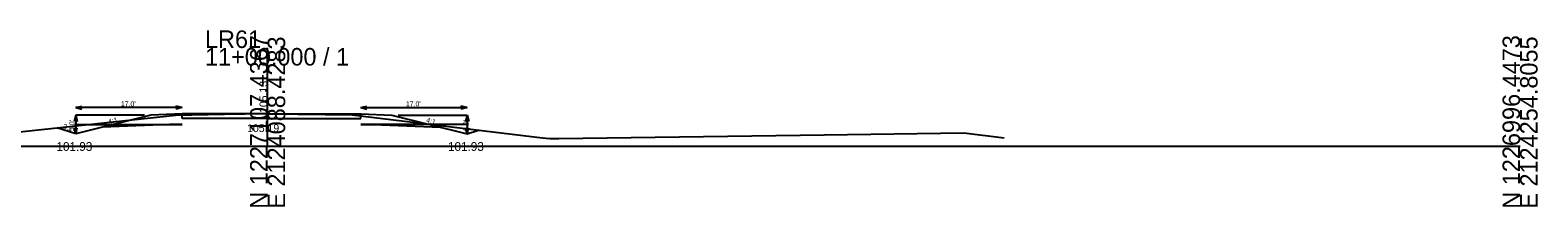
# Model space of a CAD drawing. Extents: x -26 to 1403, y -10 to 9574.
# Drawn here: x 1162.1 to 1402.8, y 990.3 to 1018.5 of the extents above; entities that cross this region are included whole.
import ezdxf

# ---------------------------------------------------------------- set-up
doc = ezdxf.new("R2010")
doc.units = 0
for name, color, linetype in [('XS_CELL', 7, 'Continuous'), ('XS_P_FINISHED_GRADE', 7, 'Continuous'), ('XS_P_FINISHED_GRADE_ELEV_TX', 7, 'Continuous'), ('XS_P_SUBGRADE_GRANULAR', 7, 'Continuous'), ('XS_P_SUBGRADE_PAVEMENT', 7, 'Continuous'), ('XS_P_TX_CLEARZONE', 7, 'Continuous'), ('XS_P_TX_DCH', 7, 'Continuous'), ('XS_P_TX_FS_BS', 7, 'Continuous'), ('XS_X_GROUND', 7, 'Continuous'), ('XS_X_GROUND_TX', 7, 'Continuous')]:
    doc.layers.add(name, color=color, linetype=linetype)

msp = doc.modelspace()

# ---------------------------------------------------------------- linework, layer by layer
at = {"layer": 'XS_CELL'}
for p, q in [((1200, 1000), (1200, 1015.64)), ((1000, 1000), (1200, 1000)), ((1200, 1000), (1400, 1000))]:
    msp.add_line(p, q, dxfattribs=at)
at = {"layer": 'XS_P_FINISHED_GRADE'}
for p, q in [((1181.35, 1004.93), (1169.35, 1001.93)), ((1186.35, 1005.13), (1181.35, 1004.93)), ((1200, 1005.13), (1186.35, 1005.13)), ((1200, 1005.13), (1214.86, 1005.13)), ((1214.86, 1005.13), (1219.86, 1004.93)), ((1219.86, 1004.93), (1231.87, 1001.93)), ((1169.35, 1001.93), (1166.36, 1002.93)), ((1231.87, 1001.93), (1233.66, 1002.53))]:
    msp.add_line(p, q, dxfattribs=at)
at = {"layer": 'XS_P_SUBGRADE_GRANULAR'}
for p, q in [((1169.15, 1003.43), (1186.35, 1003.43)), ((1184.35, 1003.43), (1173.63, 1003)), ((1186.35, 1003.43), (1184.35, 1003.43)), ((1232.07, 1003.43), (1214.86, 1003.43)), ((1214.86, 1003.43), (1216.86, 1003.43)), ((1216.86, 1003.43), (1227.58, 1003))]:
    msp.add_line(p, q, dxfattribs=at)
at = {"layer": 'XS_P_SUBGRADE_PAVEMENT'}
for p, q in [((1186.35, 1004.38), (1186.35, 1005.13)), ((1200, 1004.38), (1186.35, 1004.38)), ((1200, 1004.38), (1214.86, 1004.38)), ((1214.86, 1004.38), (1214.86, 1005.13))]:
    msp.add_line(p, q, dxfattribs=at)
at = {"layer": 'XS_P_TX_CLEARZONE'}
for p, q in [((1169.35, 1006.13), (1170.35, 1006.38)), ((1186.35, 1006.13), (1185.35, 1006.38)), ((1214.86, 1006.13), (1215.86, 1006.38)), ((1231.87, 1006.13), (1230.87, 1006.38)), ((1169.35, 1004.93), (1169.1, 1003.93)), ((1169.35, 1006.13), (1170.35, 1005.88)), ((1186.35, 1006.13), (1169.35, 1006.13)), ((1169.35, 1004.93), (1169.6, 1003.93)), ((1169.35, 1004.93), (1169.35, 1001.93)), ((1180.35, 1004.93), (1169.35, 1004.93)), ((1186.35, 1006.13), (1185.35, 1005.88)), ((1214.86, 1006.13), (1215.86, 1005.88)), ((1214.86, 1006.13), (1231.87, 1006.13)), ((1220.86, 1004.93), (1231.87, 1004.93)), ((1231.87, 1006.13), (1230.87, 1005.88)), ((1231.87, 1004.93), (1231.62, 1003.93)), ((1231.87, 1004.93), (1231.87, 1001.93)), ((1231.87, 1004.93), (1232.12, 1003.93)), ((1169.35, 1001.93), (1169.1, 1002.93)), ((1169.35, 1001.93), (1169.6, 1002.93)), ((1231.87, 1001.93), (1231.62, 1002.93)), ((1231.87, 1001.93), (1232.12, 1002.93))]:
    msp.add_line(p, q, dxfattribs=at)
at = {"layer": 'XS_X_GROUND'}
for p, q in [((1156.87, 1001.92), (1185.3, 1004.93)), ((1185.3, 1004.93), (1193.09, 1005.08)), ((1193.09, 1005.08), (1199.77, 1005.19)), ((1199.77, 1005.19), (1204.85, 1005.11)), ((1204.85, 1005.11), (1213.5, 1004.96)), ((1213.5, 1004.96), (1243.9, 1001.3)), ((1246.49, 1001.21), (1288.88, 1001.79)), ((1288.88, 1001.79), (1311.2, 1002.09)), ((1311.2, 1002.09), (1317.61, 1001.33)), ((1243.9, 1001.3), (1245.06, 1001.21)), ((1245.06, 1001.21), (1246.49, 1001.21))]:
    msp.add_line(p, q, dxfattribs=at)

# ---------------------------------------------------------------- texts
at = {"layer": 'XS_CELL'}
for s, p in [('LR61', (1190, 1015.64)), ('11+00.000 / 1', (1190, 1012.84))]:
    msp.add_text(s, height=2.8, dxfattribs=at).set_placement(p)
for s, p in [('N 1227107.4367', (1200, 990)), ('E 2124088.4283', (1202.8, 990)), ('N 1226996.4473', (1400, 990)), ('E 2124254.8055', (1402.8, 990))]:
    msp.add_text(s, height=2.8, rotation=90, dxfattribs=at).set_placement(p)
at = {"layer": 'XS_P_FINISHED_GRADE_ELEV_TX'}
msp.add_text('105.13', height=1.25, rotation=90, dxfattribs=at).set_placement((1199.95, 1005.28))
at = {"layer": 'XS_P_TX_CLEARZONE'}
for p in [(1176.56, 1006.33), (1222.08, 1006.33)]:
    msp.add_text("17.0'", height=0.8, dxfattribs=at).set_placement(p)
for p in [(1169.15, 1002.41), (1232.07, 1002.41)]:
    msp.add_text("3.0'", height=0.8, rotation=90, dxfattribs=at).set_placement(p)
at = {"layer": 'XS_P_TX_DCH'}
for p in [(1166.28, 999.23), (1228.8, 999.23)]:
    msp.add_text('101.93', height=1.4, dxfattribs=at).set_placement(p)
at = {"layer": 'XS_P_TX_FS_BS'}
for s, rotation, p in [('4:1', 14.0343, (1174.64, 1003.46)), ('4:1', 345.9663, (1225.25, 1003.79)), ('3:1', 341.5675, (1167.27, 1002.83))]:
    msp.add_text(s, height=0.8, rotation=rotation, dxfattribs=at).set_placement(p)
at = {"layer": 'XS_X_GROUND_TX'}
msp.add_text('105.19', height=1.25, rotation=360, dxfattribs=at).set_placement((1196.73, 1002.23))

doc.saveas('drawing.dxf')
